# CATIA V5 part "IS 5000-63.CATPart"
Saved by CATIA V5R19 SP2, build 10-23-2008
Part number: IS 5000-63
Bounding box of the stored display mesh (mm): x -59.975 to 59.975, y -59.975 to 59.975, z 0 to 267
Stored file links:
  C:\Users\Bora\Desktop\3D Katı model\IS serisi\IS 5000\IS 5000-63.CATPart
  C:\Program Files\Dassault Systemes\B19\intel_a\reffiles\standard\MetricThickPitch.txt
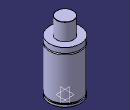
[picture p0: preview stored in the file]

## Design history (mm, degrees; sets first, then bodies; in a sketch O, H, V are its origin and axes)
Body1 (main body)
  Sketch1 on yz-plane, origin (0, 0, 0), H (0, 1, 0), V (0, 0, 1)
    point P1 (60, 181)
    point P2 (60, 176)
    point P5 (32.5, 266)
    point P7 (32.5, 266)
    point P12 (60, 176)
    point P13 (60, 181)
    arc A1 centre (60, 178.5) radius 2.5 from (60, 181) to (60, 176) ccw
    line L1 (60, 0) -> (60, 8)
    line L2 (32.5, 266) -> (32.5, 201)
    arc A2 centre (31.5, 266) radius 1 from (32.5, 266) to (31.5, 267) ccw
    line L3 (56, 13) -> (56, 8)
    line L4 (60, 13) -> (60, 176)
    line L5 (60, 181) -> (60, 201)
    line L6 (31.5, 267) -> (0, 267)
    point P15 (0, 267)
    line L7 (32.5, 201) -> (60, 201)
    line L8 (0, 0) -> (60, 0)
    line L9 (56, 13) -> (60, 13)
    line L10 (56, 8) -> (60, 8)
    coincidence: P15 V, P1 P13, P2 P12, P5 P7
    tangency: L6 A2
    horizontal: L7 H, L8 H, L9 H, L10 H
  Shaft1: profile Sketch1, axis Sketch1.V, angle 360
  Sketch2 on face of Shaft1 from Sketch1.L8, origin (0, 0, 0), H (1, 0, 0), V (0, -1, 0)
    point P1 (40, 0)
    distance P1 V = 40
  Hole1: placed by Sketch2, at (40, 0, 0) direction (0, 0, 1), diameter 8.376, depth 16, threaded "M10", thread diameter 10, thread depth 16, pitch 1.5
  CircPattern1: of Hole1, instances 4, angular step 90, axis from xy-plane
